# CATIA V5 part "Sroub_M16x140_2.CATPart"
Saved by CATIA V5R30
Part number: Sroub_M16x140_2
Definition: E 1200_16x140_1
Nomenclature: E 1200_16x140_1
Source: Unknown
Description: PART--DESC
Bounding box of the stored display mesh (mm): x 128 to 152, y 125.01 to 148.99, z -24.3 to 131.7
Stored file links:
  E:\Bakalarka\Model\Forma_v7\Sroub_M16x140_2.CATPart
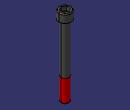
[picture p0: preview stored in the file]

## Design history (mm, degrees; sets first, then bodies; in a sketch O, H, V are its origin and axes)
Body1 "MANIFOLD_SOLID_BREP #3834" (main body)
  Solid1: solid without history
